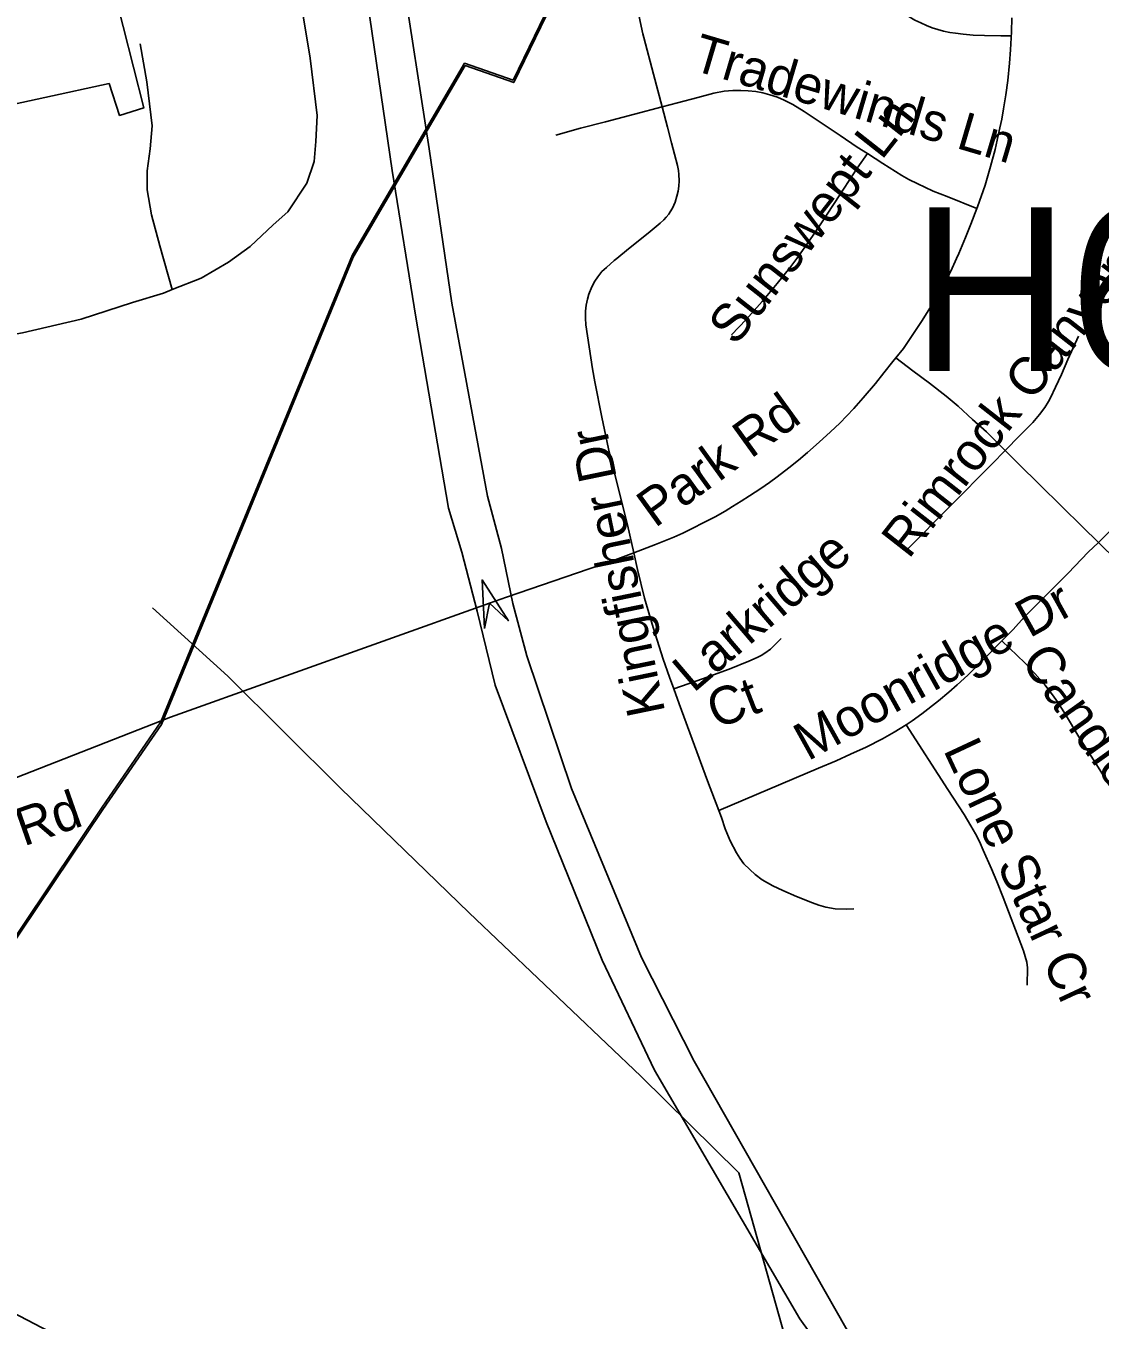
# Model space of a CAD drawing. Extents: x 1383679 to 1536984, y 460658 to 651027.
# Drawn here: x 1438807 to 1441502, y 486404 to 489649 of the extents above; entities that cross this region are included whole.
import ezdxf

# ---------------------------------------------------------------- set-up
doc = ezdxf.new("R2010")
doc.units = 0
for name, color, linetype in [('Default', 7, 'Continuous'), ('Exist Boundary Political City Limit New', 7, 'Continuous'), ('Exist Cultural Warehouse Building Footprint', 7, 'Continuous'), ('Exist Road Non-System Type 51', 7, 'Continuous'), ('Exist Road Non-System Type 51 Label', 7, 'Continuous'), ('Exist Road Primary Interstate Divided Center Attributed', 7, 'Continuous'), ('Exist Road Primary US Structure Non-Sys NCDOT Attributed CELL', 7, 'Continuous'), ('Exist Road Primary US Structure Non-Sys NCDOT Number Label', 7, 'Continuous'), ('Exist Utilities Electrical Transmission Line', 7, 'Continuous'), ('Map Preparation Boundary City Limit Buffer Line', 7, 'Continuous')]:
    doc.layers.add(name, color=color, linetype=linetype)

msp = doc.modelspace()

# ---------------------------------------------------------------- linework, layer by layer
at = {"layer": 'Default'}
msp.add_lwpolyline([(1437873, 486526), (1438365.8, 486752.5), (1438493.8, 486952.4), (1438670.6, 487193.3), (1439000.8, 487684), (1439147.6, 487897.5), (1439628.5, 489069), (1439909.4, 489549.7), (1440031.1, 489507.2), (1440708.2, 490904.6), (1441014.9, 491076.1), (1441012.1, 491081.6)], dxfattribs=at)
at = {"layer": 'Exist Boundary Political City Limit New'}
for points in [[(1441012.1, 491081.6), (1440706.6, 490910.8), (1440029.5, 489513.4), (1439907.8, 489555.8), (1439626.9, 489075.2), (1439146, 487903.7), (1438999.1, 487690.2), (1438669, 487199.5), (1438492.1, 486958.5), (1438364.1, 486758.7), (1437871.2, 486532.2), (1437873, 486526)], [(1437873, 486526), (1438365.8, 486752.5), (1438493.8, 486952.4), (1438670.6, 487193.3), (1439000.8, 487684), (1439147.6, 487897.5), (1439628.5, 489069), (1439909.4, 489549.7), (1440031.1, 489507.2), (1440708.2, 490904.6), (1441014.9, 491076.1), (1441012.1, 491081.6)]]:
    msp.add_lwpolyline(points, dxfattribs=at)
at = {"layer": 'Exist Cultural Warehouse Building Footprint'}
msp.add_lwpolyline([(1438692.5, 489434.3), (1439016, 489504.6), (1439042.6, 489425), (1439103, 489443.7), (1439025.7, 489750.6)], dxfattribs=at)
at = {"layer": 'Exist Road Non-System Type 51'}
for points in [[(1438692.7, 491243.4), (1438808.7, 491222.3), (1438892.1, 491194.1), (1438953.8, 491166), (1439011.8, 491109.7), (1439106.1, 490975.9), (1439198.6, 490784.2), (1439318.3, 490566), (1439387.2, 490354.8), (1439419.8, 490221.1), (1439431.2, 490143.7), (1439464.7, 489907.5), (1439520.4, 489568.5), (1439538.1, 489424.3), (1439534.4, 489359.4), (1439530.6, 489308.9), (1439512.1, 489254.8), (1439464.7, 489182.7), (1439427.5, 489150.3), (1439369.9, 489096.2), (1439316, 489056.5), (1439247.3, 489016.8), (1439174.8, 488988)], [(1440447.1, 489999.2), (1440421.7, 489947.3), (1440390.2, 489881), (1440383, 489866.3), (1440372.1, 489844.3), (1440363.2, 489823.9), (1440356.4, 489806.2), (1440352.9, 489796.3), (1440349.3, 489782.7), (1440346.6, 489772.3), (1440344.2, 489761), (1440342.7, 489747.8), (1440342, 489737.6), (1440341.6, 489725.8), (1440341.3, 489712.4), (1440341.8, 489700.5), (1440343.4, 489686.1), (1440348, 489660), (1440354.8, 489629.7), (1440357.4, 489619.8), (1440381.8, 489528.4), (1440403.2, 489446.5)], [(1441278.8, 489624), (1441252.9, 489624.1), (1441211.8, 489625.2), (1441183.2, 489626.4), (1441158.4, 489628.3), (1441139.1, 489630.7), (1441125.1, 489633), (1441108.9, 489636.3), (1441094.7, 489640.2), (1441080.6, 489644.7), (1441066.2, 489650.4), (1441052.4, 489656.6), (1441037.4, 489663.8), (1441018.1, 489675.1), (1440998.3, 489688.1), (1440945.7, 489725.9), (1440883.4, 489772.3), (1440844, 489803.1)], [(1441192.6, 489191.6), (1441194, 489195.3), (1441213.8, 489249.6), (1441227.1, 489296.7), (1441238.3, 489339.2), (1441246.3, 489374.7), (1441250.4, 489393.8), (1441255.1, 489415.2), (1441259.8, 489441.4), (1441265.4, 489476.7), (1441270.3, 489512.3), (1441274.8, 489555.5), (1441277.2, 489589), (1441279.6, 489634.6), (1441280.8, 489669.5)], [(1439174.8, 488988), (1439143.2, 489098), (1439122.8, 489175.5), (1439111.6, 489238.6), (1439111.6, 489285.5), (1439119.1, 489341.4), (1439124.6, 489399.1), (1439110.7, 489509), (1439094, 489604.6)], [(1440403.2, 489446.5), (1440442, 489456.7), (1440493.1, 489470), (1440533, 489481), (1440559.2, 489485.9), (1440580.9, 489487.6), (1440600.5, 489487.4), (1440619.2, 489486.8), (1440638.5, 489484.4), (1440656.1, 489481.4), (1440673.5, 489476.7), (1440692.9, 489470.2), (1440709.6, 489462.7), (1440730.9, 489452.6), (1440759.5, 489434.8), (1440794.9, 489411.4), (1440849.9, 489374.8), (1440892.9, 489344.8), (1440918, 489328.9)], [(1440136.3, 489375.7), (1440198.3, 489392.5), (1440261.1, 489408.4), (1440333.7, 489428.3), (1440403.2, 489446.5)], [(1440403.2, 489446.5), (1440416.6, 489395), (1440426.7, 489356.2), (1440442.2, 489299.4), (1440444.2, 489286.6), (1440445.4, 489276.7), (1440445.8, 489261), (1440445.2, 489247.5), (1440443.2, 489235.2), (1440440.2, 489221.9), (1440435.7, 489207.5), (1440429, 489192.3), (1440423.5, 489182.8), (1440420.2, 489177.1), (1440413.8, 489169.3), (1440407.5, 489162.7), (1440398.8, 489154.5), (1440368.5, 489129.3), (1440319.1, 489090), (1440289.9, 489066), (1440283.4, 489060.6), (1440263.5, 489043.5), (1440252.3, 489033), (1440241.7, 489020), (1440234.5, 489009.5), (1440226.6, 488994.9), (1440219.3, 488976.2), (1440216, 488964), (1440212.6, 488948.6), (1440211.2, 488934.3), (1440210.8, 488916), (1440211.7, 488900), (1440228.6, 488789.5), (1440234.3, 488756.9), (1440252.1, 488668.1), (1440269.2, 488589), (1440293.3, 488490.6), (1440316.1, 488398), (1440332.2, 488328)], [(1440918, 489328.9), (1440892.6, 489292.2), (1440848.8, 489225.5), (1440801.3, 489152.9), (1440771.3, 489108.3), (1440745.1, 489071.5), (1440741.1, 489066), (1440724, 489042.3), (1440691.8, 489003), (1440654.3, 488958.1), (1440614.2, 488913.4), (1440577.2, 488874.5)], [(1440918, 489328.9), (1440956.7, 489304.2), (1441004.4, 489274.1), (1441021.8, 489264.4), (1441044.4, 489253.3), (1441061.9, 489244.7), (1441083.4, 489235.2), (1441117.9, 489221.1), (1441192.6, 489191.6)], [(1440989.2, 488816.5), (1441008.3, 488840.3), (1441033.6, 488877.9), (1441053.6, 488907.9), (1441080.6, 488950.7), (1441105.1, 488993), (1441116.5, 489013.6), (1441127.3, 489034), (1441141.3, 489066), (1441147.2, 489078.4), (1441164.4, 489118.4), (1441177.5, 489151.7), (1441192.6, 489191.6)], [(1438546.7, 488887), (1438612.7, 488865.4), (1438662.9, 488858.2), (1438718.6, 488865.4), (1438799.4, 488879.8), (1438946.2, 488914.1), (1439074.5, 488955.5), (1439152.5, 488979), (1439174.8, 488988)], [(1441447.9, 488871.1), (1441421.1, 488812.7), (1441405.3, 488775.1), (1441390.3, 488743.2), (1441377.6, 488716.6), (1441372.8, 488707.6), (1441363, 488692), (1441349.6, 488674.6), (1441332.9, 488654.4), (1441300.6, 488621.8), (1441263.7, 488584.1)], [(1440989.2, 488816.5), (1440981.9, 488807.5), (1440959.1, 488779.3), (1440938.2, 488752.6), (1440907.6, 488716.9), (1440884.5, 488690.2), (1440849.4, 488652.8), (1440825.7, 488631), (1440797.1, 488605), (1440767.6, 488579.6), (1440745.4, 488560.4), (1440721.5, 488541.3), (1440691.7, 488518.4), (1440672.9, 488504.5), (1440650.7, 488489.1), (1440622.6, 488470.4), (1440601.7, 488457.1), (1440580.1, 488444), (1440561, 488432.4), (1440536.4, 488418.2), (1440509.5, 488405), (1440476.7, 488388.2), (1440455.4, 488377.3), (1440432.3, 488366.8), (1440387, 488348.5), (1440332.2, 488328)], [(1440989.2, 488816.5), (1441032.4, 488784.4), (1441074.3, 488753.1), (1441115.7, 488721.1), (1441145.6, 488695.7), (1441181.6, 488662.6), (1441216.9, 488631.4), (1441263.7, 488584.1)], [(1441497.4, 488354), (1441539.1, 488394.7), (1441586.2, 488442.2), (1441643.2, 488502.8), (1441653.1, 488515.6), (1441665, 488532.7), (1441672.9, 488546), (1441683.9, 488568.6), (1441701.6, 488609.3)], [(1441263.7, 488584.1), (1441231.1, 488550.8), (1441019.1, 488337.2)], [(1441263.7, 488584.1), (1441296.8, 488550.7), (1441350.6, 488498.6), (1441405, 488445), (1441457.5, 488392.9), (1441497.4, 488354)], [(1441255.3, 488107), (1441283.8, 488135.9), (1441311.5, 488166.8), (1441357.9, 488213.3), (1441421.7, 488276.9), (1441471.9, 488329.2), (1441497.4, 488354)], [(1441497.4, 488354), (1441544.4, 488308.2)], [(1440332.2, 488328), (1440279.2, 488308.1), (1440013, 488216.6), (1439970.4, 488201.8), (1439170.1, 487915.5), (1438535.8, 487667.1), (1438347.2, 487631.9), (1438245.7, 487639), (1438093.4, 487660.1), (1437954, 487731.3)], [(1440332.2, 488328), (1440341.9, 488285.7), (1440359.5, 488214.4), (1440380.5, 488140.7), (1440406, 488060.8), (1440421.8, 488015.7), (1440432.4, 487986.7)], [(1440701.5, 488112.8), (1440675, 488086.1), (1440661.3, 488076), (1440651.5, 488070.5), (1440641.6, 488065.6), (1440620.5, 488055.8), (1440571.4, 488036.5), (1440504.2, 488012.1), (1440432.4, 487986.7)], [(1441015.2, 487896.8), (1441030.1, 487906.2), (1441054.5, 487924.2), (1441096.1, 487956.7), (1441122.5, 487978.4), (1441143.1, 487996.8), (1441170.1, 488020.8), (1441207.1, 488058.2), (1441255.3, 488107)], [(1441755.8, 487446.9), (1441722.1, 487481.9), (1441697.9, 487506.9), (1441681.6, 487525.3), (1441662.8, 487545.9), (1441646.8, 487564.8), (1441633.9, 487580), (1441617.9, 487601), (1441588.6, 487643.1), (1441558.4, 487690.3), (1441528, 487740.4), (1441497.2, 487790.6), (1441448.8, 487866.3), (1441415.4, 487922.3), (1441394.6, 487954.6), (1441382.4, 487971.8), (1441363, 487996.9), (1441337.7, 488025.2), (1441313.2, 488052.4), (1441255.3, 488107)], [(1440432.4, 487986.7), (1440446.4, 487948.8), (1440517.4, 487756.3), (1440545.5, 487681.8)], [(1440545.5, 487681.8), (1440795.8, 487787.7), (1440839.5, 487806), (1440875.4, 487822.6), (1440915.3, 487840.9), (1440956, 487861.5), (1440985, 487877.8), (1441015.2, 487896.8)], [(1441319, 487243.9), (1441319.4, 487287.3), (1441318, 487301), (1441309.9, 487329.5), (1441258.6, 487463.5), (1441243, 487504), (1441229.6, 487535.7), (1441208.8, 487582.1), (1441199.4, 487603.7), (1441189.2, 487623), (1441177.4, 487643.5), (1441160.6, 487671.8), (1441120.3, 487734), (1441015.2, 487896.8)], [(1440545.5, 487681.8), (1440552, 487664.4), (1440561.6, 487635.4), (1440574.2, 487605.5), (1440590.1, 487575.8), (1440597.9, 487562.2), (1440608.6, 487548.3), (1440622.9, 487533.8), (1440636.6, 487520.9), (1440654.5, 487507.7), (1440681.3, 487493), (1440705.7, 487481.1), (1440740.1, 487466.4), (1440780.2, 487450.2), (1440796.3, 487444.3), (1440813.7, 487439.3), (1440837.3, 487435.5), (1440865.7, 487433.9), (1440883.9, 487434.9)], [(1439489.3, 486049.5), (1438332.3, 486653.7)]]:
    msp.add_lwpolyline(points, dxfattribs=at)
at = {"layer": 'Exist Road Primary Interstate Divided Center Attributed'}
for points in [[(1440029.1, 488201.1), (1440000.3, 488338.8), (1439965.1, 488470.1), (1439876.2, 488953.7), (1439818.6, 489341.2), (1439679.9, 490238.2), (1439575.9, 491007.9)], [(1439597, 490175.3), (1439725.8, 489286.8), (1439785.2, 488919.1), (1439867.9, 488439.5), (1439901.1, 488329.2), (1439939.5, 488181.9)], [(1439939.5, 488181.9), (1439984.3, 487996.2), (1440112.3, 487653.5), (1440253.1, 487306.3), (1440384.3, 487030.9), (1440749.1, 486406.5), (1441034, 486009.6), (1441270.3, 485722.8), (1441297.1, 485676.3)], [(1441341, 485777.5), (1441260.4, 485871.2), (1441054, 486122.1), (1440864.3, 486384.1), (1440483.5, 487053.4), (1440351.8, 487312.8), (1440176.3, 487736.8), (1440064.3, 488069.8), (1440029.1, 488201.1)]]:
    msp.add_lwpolyline(points, dxfattribs=at)
at = {"layer": 'Exist Road Primary US Structure Non-Sys NCDOT Attributed CELL'}
msp.add_lwpolyline([(1439957.8, 488138), (1439951.6, 488259.8), (1440017.9, 488157.4), (1439970.4, 488201.8)], close=True, dxfattribs=at)
at = {"layer": 'Exist Utilities Electrical Transmission Line'}
msp.add_lwpolyline([(1440949, 485535.8), (1440865, 485863.4), (1440711.9, 486360.3), (1440595.3, 486772.7), (1440349.7, 487015.3), (1439919.2, 487425.3), (1439596.7, 487737.4), (1439313.6, 488018.6), (1439124.8, 488190.1)], dxfattribs=at)
at = {"layer": 'Map Preparation Boundary City Limit Buffer Line'}
for points in [[(1441012.1, 491081.6), (1440706.6, 490910.8), (1440029.5, 489513.4), (1439907.8, 489555.8), (1439626.9, 489075.2), (1439146, 487903.7), (1438999.1, 487690.2), (1438669, 487199.5), (1438492.1, 486958.5), (1438364.1, 486758.7), (1437871.2, 486532.2), (1437873, 486526)], [(1437873, 486526), (1438365.8, 486752.5), (1438493.8, 486952.4), (1438670.6, 487193.3), (1439000.8, 487684), (1439147.6, 487897.5), (1439628.5, 489069), (1439909.4, 489549.7), (1440031.1, 489507.2), (1440708.2, 490904.6), (1441014.9, 491076.1), (1441012.1, 491081.6)], [(1437873, 486526), (1438365.8, 486752.5), (1438493.8, 486952.4), (1438670.6, 487193.3), (1439000.8, 487684), (1439147.6, 487897.5), (1439628.5, 489069), (1439909.4, 489549.7), (1440031.1, 489507.2), (1440708.2, 490904.6), (1441014.9, 491076.1), (1441012.1, 491081.6)]]:
    msp.add_lwpolyline(points, dxfattribs=at)

# ---------------------------------------------------------------- texts
at = {"layer": 'Exist Road Non-System Type 51 Label'}
for s, rotation, p in [('Tradewinds Ln', 343.5285, (1440474.3, 489540.1)), ('Sunswept Ln', 51.8428, (1440587.3, 488844.1)), ('Rimrock Canyon Dr', 51.9621, (1441021.6, 488310.1)), ('Park Rd', 35.8472, (1440385.2, 488388.8)), ('Kingfisher Dr', 101.6654, (1440411.4, 487928.5)), ('Larkridge', 40.531, (1440481.9, 487975)), ('Moonridge Dr', 29.0295, (1440768.9, 487804.5)), ('Candlelight Ct', 305.4379, (1441300, 488057.3)), ('Ct', 21.2512, (1440539.4, 487885.1)), ('Lone Star Cr', 295.0507, (1441107.5, 487833.8)), ('Park Rd', 19.2906, (1438522.1, 487493.3))]:
    msp.add_text(s, height=95, rotation=rotation, dxfattribs=at).set_placement(p)
at = {"layer": 'Exist Road Primary US Structure Non-Sys NCDOT Number Label'}
msp.add_text('H653', height=410.1, dxfattribs=at).set_placement((1441028.7, 488784))

doc.saveas('drawing.dxf')
